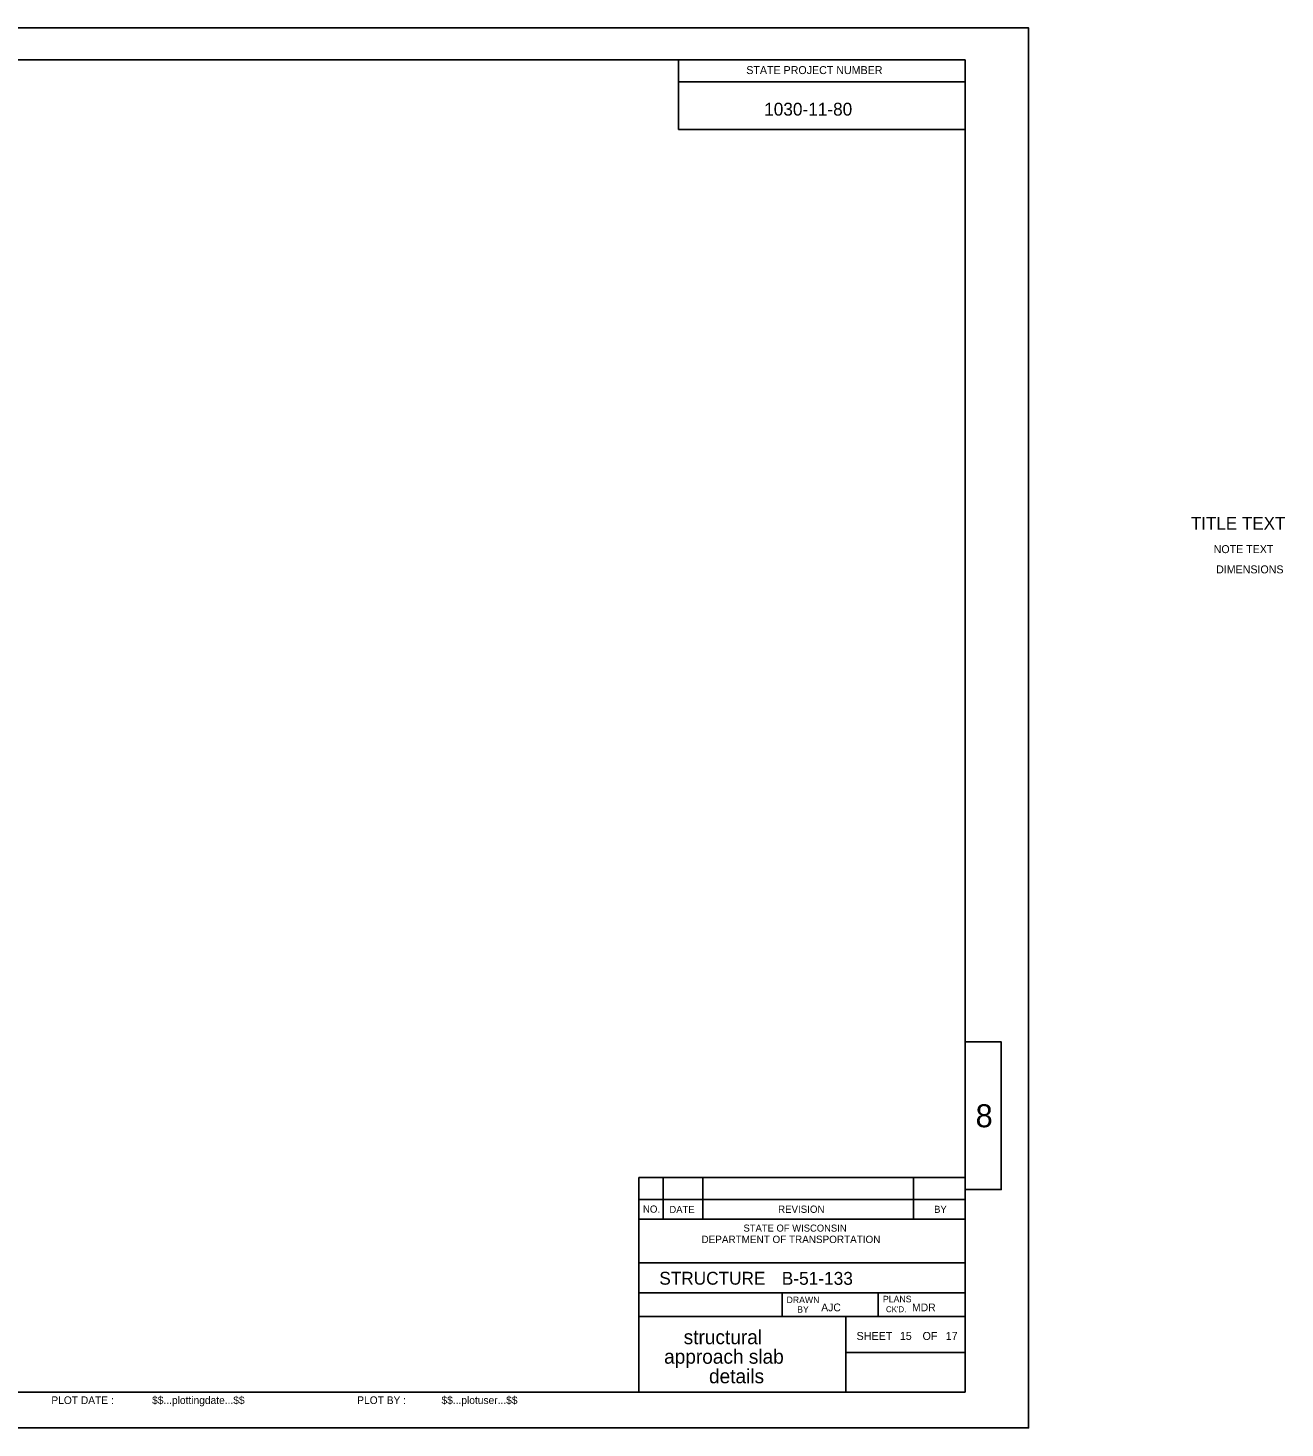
# Model space of a CAD drawing. Extents: x -1551839.2 to -1551801.2, y -1982240.1 to -1982218.1.
# Drawn here: x -1551820.91 to -1551801.15, y -1982240.08 to -1982218.08 of the extents above; entities that cross this region are included whole.
import ezdxf

# ---------------------------------------------------------------- set-up
doc = ezdxf.new("R2010")
doc.units = 0
for name, color, linetype in [('b_dimension', 7, 'Continuous'), ('b_ghost', 7, 'Continuous'), ('b_text', 7, 'Continuous'), ('b_title text', 7, 'Continuous'), ('Level 59', 7, 'Continuous'), ('PLT_Sheet_Info', 7, 'Continuous')]:
    doc.layers.add(name, color=color, linetype=linetype)

msp = doc.modelspace()

# ---------------------------------------------------------------- linework, layer by layer
at = {"layer": 'b_ghost'}
msp.add_lwpolyline([(-1551839.182, -1982218.084), (-1551805.183, -1982218.084), (-1551805.183, -1982240.084), (-1551839.182, -1982240.084)], close=True, dxfattribs=at)
at = {"layer": 'Level 59'}
for p, q in [((-1551805.182, -1982218.084), (-1551805.737, -1982218.084)), ((-1551805.182, -1982218.539), (-1551805.182, -1982218.084)), ((-1551806.178, -1982218.584), (-1551837.12, -1982218.584)), ((-1551810.684, -1982218.584), (-1551810.684, -1982219.68)), ((-1551806.178, -1982239.522), (-1551806.178, -1982218.584)), ((-1551810.684, -1982218.929), (-1551806.178, -1982218.929)), ((-1551810.684, -1982219.68), (-1551806.178, -1982219.68)), ((-1551811.306, -1982236.147), (-1551806.178, -1982236.147)), ((-1551811.306, -1982236.803), (-1551811.306, -1982236.147)), ((-1551810.927, -1982236.803), (-1551810.927, -1982236.147)), ((-1551810.303, -1982236.803), (-1551810.303, -1982236.147)), ((-1551806.991, -1982236.803), (-1551806.991, -1982236.147)), ((-1551811.306, -1982236.491), (-1551806.178, -1982236.491)), ((-1551811.306, -1982239.522), (-1551811.306, -1982236.803)), ((-1551811.306, -1982236.803), (-1551806.178, -1982236.803)), ((-1551811.306, -1982237.49), (-1551806.178, -1982237.49)), ((-1551811.306, -1982237.959), (-1551806.178, -1982237.959)), ((-1551809.056, -1982238.334), (-1551809.056, -1982237.959)), ((-1551807.549, -1982238.334), (-1551807.549, -1982237.959)), ((-1551811.306, -1982238.334), (-1551806.178, -1982238.334)), ((-1551808.056, -1982239.522), (-1551808.056, -1982238.334)), ((-1551808.056, -1982238.897), (-1551806.182, -1982238.897)), ((-1551837.12, -1982239.522), (-1551806.178, -1982239.522)), ((-1551805.182, -1982240.084), (-1551805.182, -1982239.721)), ((-1551805.8, -1982240.084), (-1551805.182, -1982240.084))]:
    msp.add_line(p, q, dxfattribs=at)
msp.add_lwpolyline([(-1551806.178, -1982234.017), (-1551805.611, -1982234.017), (-1551805.611, -1982236.338), (-1551806.178, -1982236.338)], close=True, dxfattribs=at)

# ---------------------------------------------------------------- texts
at = {"layer": 'b_dimension'}
msp.add_text('DIMENSIONS', height=0.125, dxfattribs=at).set_placement((-1551802.235, -1982226.654))
at = {"layer": 'b_text'}
msp.add_text('NOTE TEXT', height=0.125, dxfattribs=at).set_placement((-1551802.273, -1982226.336))
at = {"layer": 'b_title text'}
msp.add_text('TITLE TEXT', height=0.2, dxfattribs=at).set_placement((-1551802.632, -1982225.967))
at = {"layer": 'Level 59'}
for s, height, p in [('STATE PROJECT NUMBER', 0.12525, (-1551809.619, -1982218.808)), ('1030-11-80', 0.2023, (-1551809.338, -1982219.461)), ('8', 0.361, (-1551806.015, -1982235.358)), ('NO.', 0.1139, (-1551811.244, -1982236.701)), ('DATE', 0.1109, (-1551810.827, -1982236.706)), ('REVISION', 0.1142, (-1551809.12, -1982236.703)), ('BY', 0.1108, (-1551806.667, -1982236.703)), ('STATE OF WISCONSIN', 0.11076, (-1551809.663, -1982236.998)), ('DEPARTMENT OF TRANSPORTATION', 0.11643, (-1551810.323, -1982237.178)), ('STRUCTURE', 0.2022, (-1551810.986, -1982237.832)), ('B-51-133', 0.2031, (-1551809.061, -1982237.834)), ('DRAWN', 0.1022, (-1551808.986, -1982238.122)), ('PLANS', 0.1023, (-1551807.471, -1982238.109)), ('BY', 0.102, (-1551808.819, -1982238.272)), ('AJC', 0.1218, (-1551808.441, -1982238.25)), ("CK'D.", 0.0927, (-1551807.424, -1982238.264)), ('MDR', 0.1218, (-1551807.014, -1982238.25)), ('structural', 0.2239, (-1551810.603, -1982238.767)), ('SHEET', 0.1262, (-1551807.886, -1982238.701)), ('15', 0.125, (-1551807.205, -1982238.7)), ('OF', 0.1262, (-1551806.849, -1982238.701)), ('17', 0.125, (-1551806.484, -1982238.7)), ('approach slab', 0.22392, (-1551810.911, -1982239.074)), ('details', 0.2239, (-1551810.205, -1982239.381))]:
    msp.add_text(s, height=height, dxfattribs=at).set_placement(p)
at = {"layer": 'PLT_Sheet_Info'}
for s, p in [('PLOT DATE :', (-1551820.541, -1982239.707)), ('$$...plottingdate...$$', (-1551818.958, -1982239.707)), ('PLOT BY :', (-1551815.734, -1982239.707)), ('$$...plotuser...$$', (-1551814.41, -1982239.707))]:
    msp.add_text(s, height=0.12, rotation=360, dxfattribs=at).set_placement(p)

doc.saveas('drawing.dxf')
